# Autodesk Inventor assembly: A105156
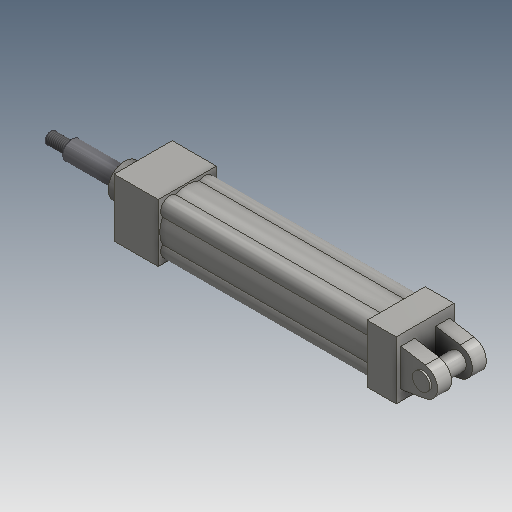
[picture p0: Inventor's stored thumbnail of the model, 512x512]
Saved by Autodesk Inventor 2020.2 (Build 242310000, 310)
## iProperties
Created: 2000-02
Part Number: A105156
Description: CYL,CLEV,MP1,1.50BX6.00S,0.63 ROD
Document SubType Name: Assembly
Designer: sspink
Mass: 840.098 g
Surface Area: 1054 cm^2
Volume: 245.292 cm^3
Density: 3.42488 g/cm^3
Control State: 0
Checked Out: False
Master: False
Shininess: 0.0
Length Units: 11269
Angle Units: 11279
Time Units: 11290
Mass Units: 11283
Length Display Precision: 3
Angle Display Precision: 2
Compacted: True
Dimensions: 50x50x355 mm
Mass: 0,84 kg
Density: 0.0
Volumn: 0.0
Area: 0.0
PropertySet Name: Model Information
Author: sspink
Revision Number: -
Title: CYL,CLEV,MP1,1.50BX6.00S,0.63 ROD
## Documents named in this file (3)
- D:\07 - DEMODATEN\OTX 2019 - Dataset - UPDATE - Dez2019\Designs\07-Packing machine\A105156.iam
- D:\07 - DEMODATEN\OTX 2019 - Dataset - UPDATE - Dez2019\Designs\07-Packing machine\Parts\ADSK-011790.ipt
- D:\07 - DEMODATEN\OTX 2019 - Dataset - UPDATE - Dez2019\Designs\07-Packing machine\Parts\ADSK-011791.ipt
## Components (2 placed, 2 different names)
1. ADSK-011790:1 — Mate:2, Passend:4
2. ADSK-011791:1 — Passend:4
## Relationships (2: Mate 2)
- Mate:2: ADSK-011790:1
- Passend:4 [Mate]: ADSK-011790:1 ↔ ADSK-011791:1
